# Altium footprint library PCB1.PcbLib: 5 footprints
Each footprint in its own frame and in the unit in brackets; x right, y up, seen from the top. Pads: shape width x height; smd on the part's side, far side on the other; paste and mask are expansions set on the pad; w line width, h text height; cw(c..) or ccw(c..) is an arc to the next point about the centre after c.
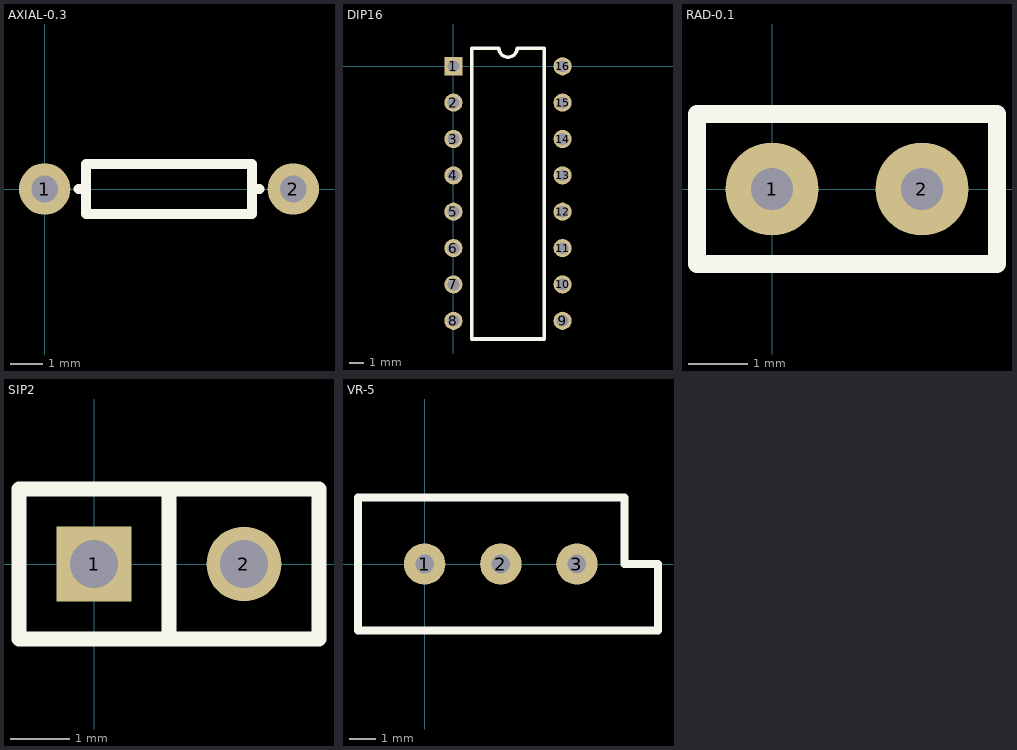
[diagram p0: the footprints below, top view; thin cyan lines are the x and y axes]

## AXIAL-0.3 [mil]
pads (2):
  round 62 hole 32: 1(0,0) 2(300,0)
Top Overlay:
  lines w12: 41,0 50,0 ; 259,0 250,0 ; 250,0 250,-30 50,-30 50,30 250,30 250,0

## DIP16 [mil]
pads (16):
  rect 50x50 hole 32: 1(0,0)
  round 50 hole 32: 2(0,-100) 3(0,-200) 4(0,-300) 5(0,-400) 6(0,-500) 7(0,-600) 8(0,-700) 9(300,-700) 10(300,-600) 11(300,-500) 12(300,-400) 13(300,-300) 14(300,-200) 15(300,-100) 16(300,0)
Top Overlay:
  lines w10: 50,-750 250,-750 250,50 175,50 cw(c150,50) 125,50 50,50 50,-750

## RAD-0.1 [mil]
pads (2):
  round 62 hole 28: 1(0,0) 2(100,0)
Top Overlay:
  lines w12: -50,-50 -50,50 150,50 150,-50 -50,-50

## SIP2 [mil]
pads (2):
  rect 50x50 hole 32: 1(0,0)
  round 50 hole 32: 2(100,0)
Top Overlay:
  lines w10: 50,-50 50,50 ; -50,-50 150,-50 150,50 -50,50 -50,-50

## VR-5 [mil]
pads (3):
  round 62 hole 28: 1(0,0) 2(114.17,0) 3(228.35,0)
Top Overlay:
  lines w12: -100,-100 350,-100 350,0 300,0 300,100 -100,100 -100,-100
